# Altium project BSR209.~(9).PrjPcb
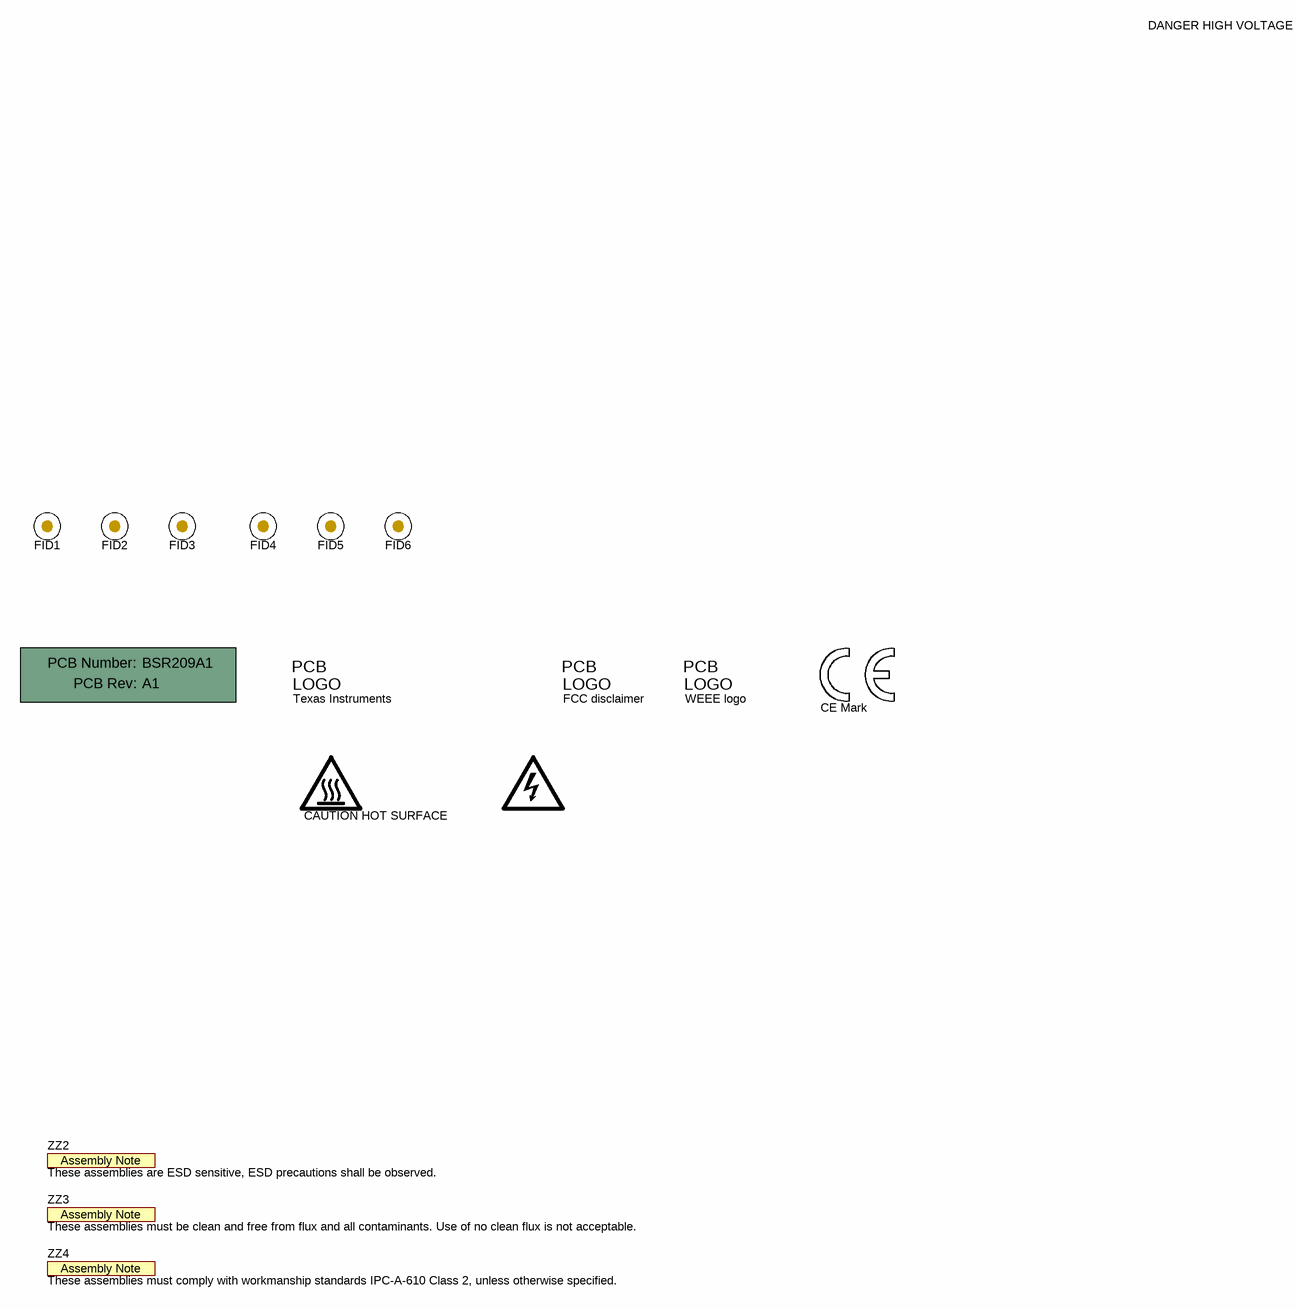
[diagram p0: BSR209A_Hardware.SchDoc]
EVM_orderable: LM5168FEVM; TID: N/A; TechSupport: http://www.ti.com/support; SCH_Rev: A1; PRJ_Title: LM5168FEVM; PRJ_Number: BSR209A1; PRJ_Engineer: FJD; PRJ_Customer: Public Release; PCB_Rev: A1; PCB_Layout: FJD; CopyrightYear: 2021
2 sheets, 69 parts. Net scope: global (net labels, ports and power ports of the same name join across sheets).
Board file: BSR209A_PCB.PcbDoc
Sheets:
  BSR209A_Hardware.SchDoc
  BSR209A_sch.SchDoc

## Sheet BSR209A_Hardware.SchDoc
size 431 x 279 mm; Date: Not shown in title block; ApprovedBy: Not shown in title block; CheckedBy: Not shown in title block; Author: Not shown in title block; CompanyName: Not shown in title block; Engineer: Not shown in title block; Organization: Not shown in title block; Address1: Not shown in title block; Address2: Not shown in title block; Address3: Not shown in title block; Address4: Not shown in title block; DocumentNumber: 1; Revision: Use project parameter SCH_Rev; SheetNumber: 2; SheetTotal: 2; PageSetup: Record=PageOptions¦CenterHorizontal=True¦CenterVertical=True¦PrintScale=1.00¦XCorrection=1.00¦YCorrection=1.00¦PrintKind=0¦BorderSize=5000000¦LeftOffset=0¦BottomOffset=0¦Orientation=2¦PaperLength=1000¦PaperWidth=1000¦Scale=100¦PaperSource=15¦PrintQuality=600¦MediaType=1¦DitherType=10¦PaperKind=Letter¦PrintScaleMode=1

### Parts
!PCB  Printed Circuit Board  (value not drawn)  (mechanical)
FID1  Fiducial  [Fiducial10-20]  (value not drawn)
FID2  Fiducial  [Fiducial10-20]  (value not drawn)
FID3  Fiducial  [Fiducial10-20]  (value not drawn)
FID4  Fiducial  [Fiducial10-20]  (value not drawn)
FID5  Fiducial  [Fiducial10-20]  (value not drawn)
FID6  Fiducial  [Fiducial10-20]  (value not drawn)
Logo1  Texas Instruments  [TI_Stacked_Overlay_Small]  (no BOM)
Logo2  CE Mark  [CE_Mark_10mm]  (no BOM)
Logo3  FCC disclaimer  [FCC_disclaimer]  (no BOM)
Logo4  WEEE logo  [WEEE_Minimum]  (no BOM)
Logo5  DANGER HIGH VOLTAGE  [IEC_HighVoltage_Small]  (no BOM)
Logo6  CAUTION HOT SURFACE  [IEC_HotSurface_Small]  (no BOM)
ZZ2  These assemblies are ESD sensitive, ESD precautions shall be observed.  [AssemblyNote]  (no BOM)
ZZ3  These assemblies must be clean and free from flux and all contaminants. Use of no clean flux is not acceptable.  [AssemblyNote]  (no BOM)
ZZ4  These assemblies must comply with workmanship standards IPC-A-610 Class 2, unless otherwise specified.  [AssemblyNote]  (no BOM)

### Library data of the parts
!PCB = CMP-0003618-2: Manufacturer: Any; PartNumber: BSR209A1; CompType: PCB
FID1-FID6 = CMP-0077181-1: Fiducial mark.  There is nothing to buy or mount.
Logo1 = CMP-0074838-1: Texas Instrument Corporate Signature; SymbolCreator: a0412235; Lib Reference: TI_Logo; Library Reference: Logo
Logo2 = CMP-0074844-1: SymbolCreator: a0412235
Logo3 = CMP-0074847-1: FCC_disclaimer; Library Reference: Logo
Logo4 = CMP-0074769-1
Logo5 = IEC_HighVoltage: IEC 61010-1 High Voltage Warning; SymbolCreator: a0412235
Logo6 = IEC_HotSurface: IEC 61010-1 Hot Surface Warning; SymbolCreator: a0412235
ZZ2 = CMP-0077236-1
ZZ3 = CMP-0077237-1
ZZ4 = CMP-0077238-1

## Sheet BSR209A_sch.SchDoc
size 431 x 279 mm; Date: Not shown in title block; ApprovedBy: Not shown in title block; CheckedBy: Not shown in title block; Author: Not shown in title block; CompanyName: Not shown in title block; Engineer: Not shown in title block; Organization: Not shown in title block; Address1: Not shown in title block; Address2: Not shown in title block; Address3: Not shown in title block; Address4: Not shown in title block; DocumentNumber: 1; Revision: Use project parameter SCH_Rev; SheetNumber: 1; SheetTotal: 2; PageSetup: Record=PageOptions¦CenterHorizontal=True¦CenterVertical=True¦PrintScale=0.96¦XCorrection=1.00¦YCorrection=1.00¦PrintKind=0¦BorderSize=5000000¦LeftOffset=0¦BottomOffset=0¦Orientation=2¦PaperLength=1000¦PaperWidth=1000¦Scale=100¦PaperSource=15¦PrintQuality=-3¦MediaType=1¦DitherType=10¦PrintScaleMode=1¦PaperKind=11×17¦PaperIndex=17
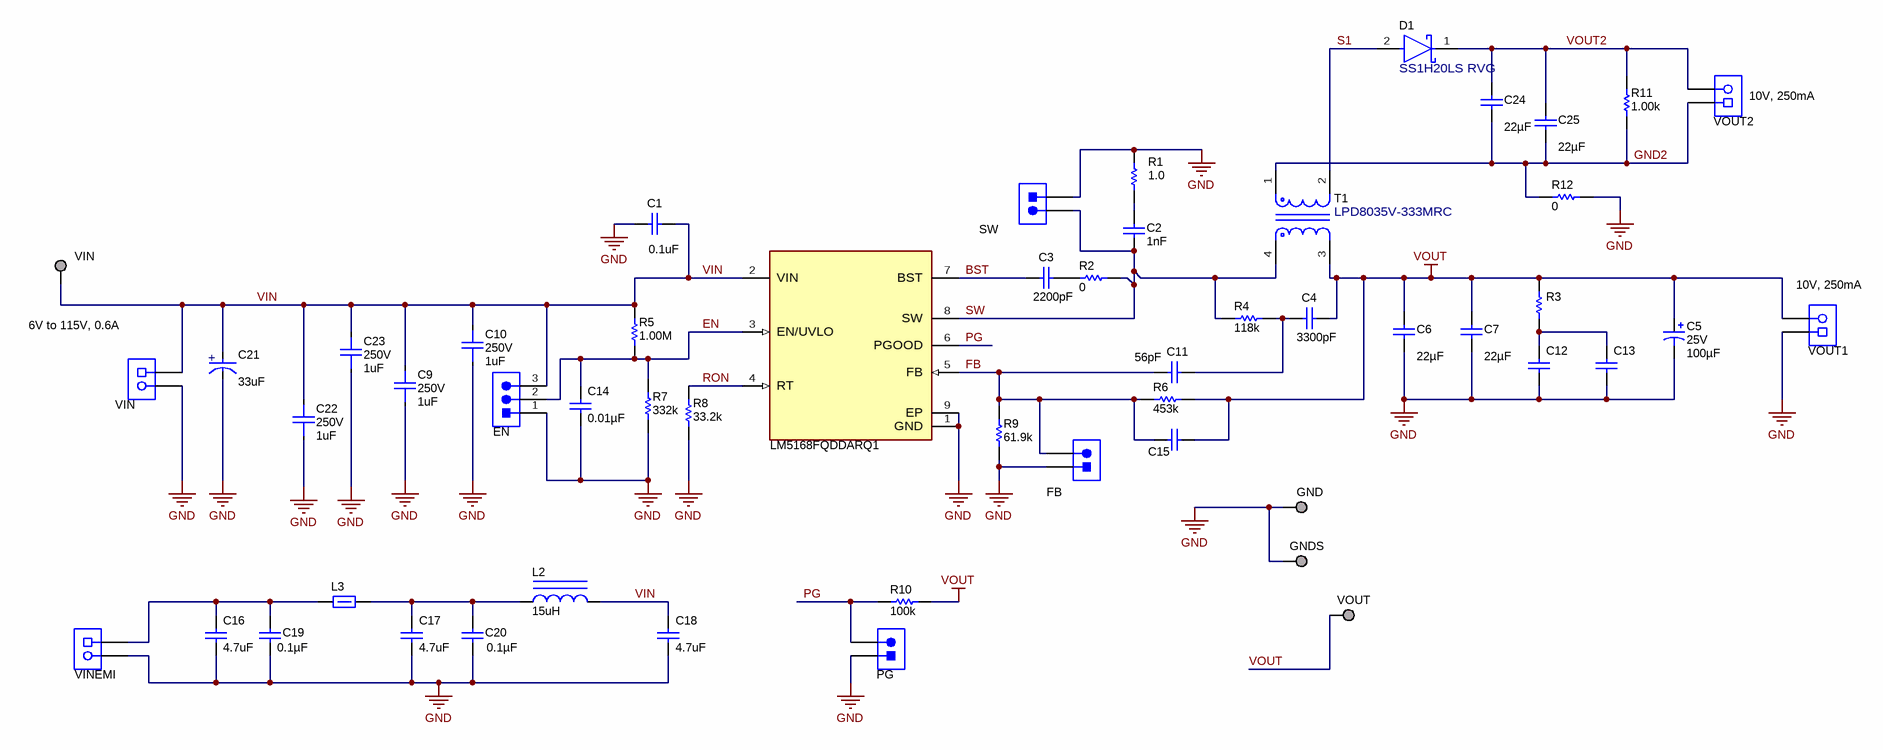
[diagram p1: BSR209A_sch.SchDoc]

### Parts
C1  ValueDisplayed: 0.1uF  [0805L]  (hidden comment: C2012X7T2E104K125AA)
C2  Cap_F: 1nF  [0603L]  (hidden comment: GRM188R72D102KW07D)
C3  ValueDisplayed: 2200pF  [0402S]  (hidden comment: GCM155R71H222KA37D)
C4  ValueDisplayed: 3300pF  [0603L]  (hidden comment: CR)
C5  VDC_V: 25V  ValueDisplayed: 100µF  [UWT_630x770]  (hidden comment: UWT1E101MCL1GS)
C6  ValueDisplayed: 22µF  [1210_270L]  (hidden comment: GRT32ER61E226KE13L)
C7  ValueDisplayed: 22µF  [1210_270L]  (hidden comment: GRT32ER61E226KE13L)
C9  VDC_V: 250V  ValueDisplayed: 1uF  [FP-CGA8P3X7T2E105K250KE_1812-MFG]  (hidden comment: CGA8P3X7T2E105K250KE)
C10  VDC_V: 250V  ValueDisplayed: 1uF  [FP-CGA8P3X7T2E105K250KE_1812-MFG]  (hidden comment: CGA8P3X7T2E105K250KE)
C11  ValueDisplayed: 56pF  [0603L]  (hidden comment: C0603C560J5GACTU)
C12  COUT3  [1210_270L]  (value not drawn)
C13  COUT4  [1210_270L]  (value not drawn)
C14  ValueDisplayed: 0.01µF  [0603L]  (hidden comment: CEN)
C15  CFF  [0603L]  (value not drawn)
C16  ValueDisplayed: 4.7uF  [1210_220]  (hidden comment: CGA6M3X7S2A475K200AB)
C17  ValueDisplayed: 4.7uF  [1210_220]  (hidden comment: CGA6M3X7S2A475K200AB)
C18  ValueDisplayed: 4.7uF  [1210_220]  (hidden comment: CGA6M3X7S2A475K200AB)
C19  ValueDisplayed: 0.1µF  [0603_HV]  (hidden comment: HMK107B7104KAHT)
C20  ValueDisplayed: 0.1µF  [0603_HV]  (hidden comment: HMK107B7104KAHT)
C21  ValueDisplayed: 33uF  [FP-ULT2C330MNL1GS_RADIAL-MFG]  (hidden comment: ULT2C330MNL1GS)
C22  VDC_V: 250V  ValueDisplayed: 1uF  [FP-CGA8P3X7T2E105K250KE_1812-MFG]  (hidden comment: CGA8P3X7T2E105K250KE)
C23  VDC_V: 250V  ValueDisplayed: 1uF  [FP-CGA8P3X7T2E105K250KE_1812-MFG]  (hidden comment: CGA8P3X7T2E105K250KE)
C24  ValueDisplayed: 22µF  [1210_270L]  (hidden comment: GRT32ER61E226KE13L)
C25  ValueDisplayed: 22µF  [1210_270L]  (hidden comment: GRT32ER61E226KE13L)
D1  SS1H20LS RVG  [FP-SS1H20LS RVG_SOD123HE-MFG]
J1  SW  [TSW-102-07-G-S]
J2  VOUT1  [TERM_BLK_ED555-2DS]
J3  VIN  [TERM_BLK_ED555-2DS]
J4  EN  [Samtec_HTSW-103-07-G-S]
J5  FB  [TSW-102-07-G-S]
J6  PG  [TSW-102-07-G-S]
J7  VINEMI  [TERM_BLK_ED555-2DS]
J8  VOUT2  [TERM_BLK_ED555-2DS]
L2  ValueDisplayed: 15uH  [MSS7341]  (hidden comment: MSS7341T-153MLB)
L3  FBMH3225HM202NT  [1210_280]  (value not drawn)
R1  ValueDisplayed: 1.0  [0603L]  (hidden comment: CRCW06031R00JNEA)
R2  ValueDisplayed: 0  [0402S]  (hidden comment: RBST)
R3  DNP  [2010]  (value not drawn)
R4  ValueDisplayed: 118k  [0603L]  (hidden comment: RC0603FR-07118KL)
R5  ValueDisplayed: 1.00M  [0603L]  (hidden comment: RC0603FR-071ML)
R6  ValueDisplayed: 453k  [0603L]  (hidden comment: RC0603FR-07453KL)
R7  ValueDisplayed: 332k  [0603L]  (hidden comment: RC0603FR-07332KL)
R8  ValueDisplayed: 33.2k  [0603L]  (hidden comment: RC0603FR-0733K2L)
R9  ValueDisplayed: 61.9k  [0603L]  (hidden comment: RC0603FR-0761K9L)
R10  ValueDisplayed: 100k  [0402S]  (hidden comment: ERJ-2RKF1003X)
R11  ValueDisplayed: 1.00k  [0805L]  (hidden comment: CRCW08051K00FKEA)
R12  ValueDisplayed: 0  [0603L]  (hidden comment: Rtie)
T1  LPD8035V-333MRC  [FP-LPD8035V-333MRC_SMD4-MFG]
TP1  VIN  [Harwin_S1751-46]
TP2  GND  [Keystone1598-2]
TP3  GNDS  [Keystone1598-2]
TP4  VOUT  [Keystone1598-2]
U1  LM5168FQDDARQ1  [DDA0008E-MFG]

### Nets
GND: C1.2 C5.2(-) C6.2 C7.2 C9.1 C10.1 C12.2 C13.2 C14.2 C16.2 C17.2 C18.2 C19.2 C20.2 C21.1(CATHODE) C22.1 C23.1 J1.1 J2.1 J3.2 J4.1 J5.1 J6.1 J7.2 R1.1 R7.1 R8.1 R9.1 R12.2 TP2.1 TP3.1 U1.1(GND) U1.9(EP)
VOUT: C4.1 C5.1(+) C6.1 C7.1 C15.1 J2.2 R3.2 R6.2 R10.2 T1.3 TP4.1
BST: C3.2 U1.7(BST)
EN: C14.1 J4.2 R5.1 R7.2 U1.3(EN/UVLO)
FB: C11.2 C15.2 J5.2 R6.1 R9.2 U1.5(FB)
GND2: C24.2 C25.2 J8.1 R11.1 R12.1 T1.1
PG: J6.2 R10.1 U1.6(PGOOD)
RON: R8.2 U1.4(RT)
S1: D1.2(ANODE) T1.2
SW: C2.2 J1.2 R2.2 R4.1 T1.4 U1.8(SW)
VIN: C1.1 C9.2 C10.2 C18.1 C21.2(ANODE) C22.2 C23.2 J3.1 J4.3 L2.2 R5.2 TP1.1 U1.2(VIN)
VOUT2: C24.1 C25.1 D1.1(CATHODE) J8.2 R11.2
NetC2_1: C2.1 R1.2
NetC3_1: C3.1 R2.1
NetC4_2: C4.2 C11.1 R4.2
NetC12_1: C12.1 C13.1 R3.1
NetC16_1: C16.1 C19.1 J7.1 L3.1
NetC17_1: C17.1 C20.1 L2.1 L3.2

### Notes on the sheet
- (near J8) 10V, 250mA
- (near J2) 10V, 250mA
- 6V to 115V, 0.6A

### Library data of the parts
C1 = CMP-0007897-1: CAP, CERM, 0.1 uF, 250 V, +/- 10%, X7T, 0805; Manufacturer: TDK; TaMin_C: -55°C; Polarized: N; SizeAreaWB_mm2: 6.75; Value1: Unknown; U/M: EA; Value: 0.1uF; TaMax_C: 125°C; SizeZ_mm: 1.45; SizeX_mm: 2; SizeY_mm: 1.25; Cap_Case: 0805; Value2: 250V; SizeArea_mm2: 2.5; CompType: Capacitor; Cap_F: 100nF; AEC Category: Q200
C2 = CMP-0081318-1: CAP, CERM, 1000 pF, 200 V,+/- 10%, X7R, 0603; Manufacturer: MuRata; SizeAreaWB_mm2: 4.68; SizeArea_mm2: 1.28; AEC Qualified: N; AEC Category: Q200; Value: 1000pF; TaMax_C: 125°C; SizeZ_mm: 1; TaMin_C: -55°C; VDC_V: 200V; SizeY_mm: 0.8; U/M: EA; CompType: Capacitor; SizeX_mm: 1.6; Cap_Case: 0603
C3 = CMP-0006357-2: CAP, CERM, 2200 pF, 50 V, +/- 10%, X7R, AEC-Q200 Grade 1, 0402; Manufacturer: MuRata; TaMin_C: -55°C; Polarized: N; SizeAreaWB_mm2: 3; Value1: Unknown; U/M: EA; Value: 2200pF; TaMax_C: 125°C; SizeZ_mm: 0.6; SizeX_mm: 1; SizeY_mm: 0.5; Cap_Case: 0402; Value2: 50V; CompType: Capacitor; AEC Qualified: Y; Cap_F: 2.2nF; AEC Category: Q200
C4 = CMP-0007087-4: CAP, CERM, 3300 pF, 100 V, +/- 10%, X7R, AEC-Q200 Grade 1, 0603; PartNumber: CGA3E2X7R2A332K080AA; Manufacturer: TDK; Polarized: N; CompType: Capacitor; Value: 3300pF; U/M: EA; Cap_F: 3.3nF; ESR_ohm: 6.62155d; Value1: 0.662155 ohm; VDC_V: 100V; IRMS_A: 3.0254dA; TaMin_C: -55°C; TaMax_C: 125°C; Cap_Case: 0603; SizeArea_mm2: 1.28; SizeAreaWB_mm2: 4.68; SizeX_mm: 1.6; SizeY_mm: 0.8; SizeZ_mm: 1; AEC Category: Q200; AEC Qualified: Y
C5 = CMP-0081462-1: CAP, AL, 100 µF, 25 V, +/- 20%, SMD; Manufacturer: Nichicon; TaMin_C: -55°C; Polarized: Y; SizeAreaWB_mm2: 77.4; U/M: EA; Value: 100uF; TaMax_C: 105°C; SizeZ_mm: 8; SizeX_mm: 7; SizeY_mm: 6.6; Cap_Case: 6.3x7.7mm; SizeArea_mm2: 46.2; CompType: Capacitor; AEC Qualified: N; IRMS_A: 91mA; AEC Category: Q200
C6 C7 C24 C25 = CMP-0084059-1: CAP, CERM, 22 µF, 25 V,+/- 10%, X5R, AEC-Q200 Grade 3, 1210; Manufacturer: MuRata; SizeAreaWB_mm2: 14.7; SizeArea_mm2: 8; AEC Qualified: Y; AEC Category: Q200; Value: 22uF; TaMax_C: 85°C; SizeZ_mm: 2.7; AEC Grade: 3; Polarized: N; TaMin_C: -55°C; VDC_V: 25V; SizeY_mm: 2.5; U/M: EA; CompType: Capacitor; SizeX_mm: 3.2; Cap_Case: 1210
C9 C10 C22 C23 = CMP-0091301-1: Cap Ceramic 1uF 250V X7T 10% Pad SMD 1812 +125°C Automotive T/R; Manufacturer: TDK; TempCo: +22/-33%; Cap_F: 1µF; AEC Qualified: Yes; Value: 1µF; AEC Grade: Grade 1; Tolerance_%: 0.1%; SizeZ_mm: 3.5mm
C11 = CMP-0006952-4: CAP, CERM, 56 pF, 50 V, +/- 5%, C0G/NP0, 0603; Manufacturer: Kemet; TaMin_C: -55°C; Polarized: N; SizeAreaWB_mm2: 4.68; Value1: Unknown; U/M: EA; Value: 56pF; TaMax_C: 125°C; SizeZ_mm: 1; SizeX_mm: 1.6; SizeY_mm: 0.8; Cap_Case: 0603; Value2: 50V; SizeArea_mm2: 1.28; CompType: Capacitor; AEC Category: Q200
C12 C13 = CMP-0009255-2: CAP, CERM, 22 uF, 25 V, +/- 10%, X7R, AEC-Q200 Grade 1, 1210; PartNumber: TMK325B7226KMHT; Manufacturer: Taiyo Yuden; Polarized: N; CompType: Capacitor; Value: 22uF; U/M: EA; Cap_F: 22µF; Value1: Unknown; VDC_V: 25V; TaMin_C: -55°C; TaMax_C: 125°C; Cap_Case: 1210; AEC Category: Q200; AEC Qualified: Y; AEC Grade: 1; SizeArea_mm2: 8; SizeAreaWB_mm2: 14.7; SizeX_mm: 3.2; SizeY_mm: 2.5; SizeZ_mm: 2.7
C14 = CMP-0080063-1: CAP, CERM, 0.01 µF, 100 V,+/- 10%, X8R, AEC-Q200 Grade 0, 0603; Manufacturer: TDK; PartNumber: CGA3E2X8R2A103K080AD; TaMin_C: -55°C; Polarized: N; SizeAreaWB_mm2: 4.68; U/M: EA; Value: 0.01uF; TaMax_C: 150°C; SizeZ_mm: 1; SizeX_mm: 1.6; SizeY_mm: 0.8; Cap_Case: 0603; Value2: 100V; SizeArea_mm2: 1.28; CompType: Capacitor; AEC Qualified: Y; Cap_F: 10nF; AEC Grade: 0; AEC Category: Q200
C15 = CMP-0006844-4: CAP, CERM, 1000 pF, 50 V, +/- 5%, X7R, AEC-Q200 Grade 1, 0603; Manufacturer: Kemet; PartNumber: C0603C102J5RACAUTO; TaMin_C: -55°C; Polarized: N; SizeAreaWB_mm2: 4.68; Value1: Unknown; U/M: EA; Value: 1000pF; TaMax_C: 125°C; SizeZ_mm: 1; SizeX_mm: 1.6; SizeY_mm: 0.8; Cap_Case: 0603; Value2: 50V; SizeArea_mm2: 1.28; CompType: Capacitor; AEC Qualified: Y; Cap_F: 1nF; AEC Category: Q200
C16-C18 = CMP-0009150-2: CAP, CERM, 4.7 uF, 100 V, +/- 10%, X7S, AEC-Q200 Grade 1, 1210; Manufacturer: TDK; TaMin_C: -55°C; ESR_ohm: 4.236m; Polarized: N; SizeAreaWB_mm2: 14.7; Value1: 0.004236 ohm; U/M: EA; Value: 4.7uF; TaMax_C: 125°C; SizeZ_mm: 2.2; SizeX_mm: 3.2; SizeY_mm: 2.5; Value2: 100V; SizeArea_mm2: 8; CompType: Capacitor; AEC Qualified: Y; Cap_F: 4.7µF; IRMS_A: 3.57337A; AEC Grade: 1; AEC Category: Q200
C19 C20 = CMP-0081011-1: CAP, CERM, 0.1 µF, 100 V,+/- 10%, X7R, AEC-Q200 Grade 1, 0603; Manufacturer: Taiyo Yuden; TaMin_C: -55°C; Polarized: N; SizeAreaWB_mm2: 4.68; U/M: EA; Value: 0.1uF; TaMax_C: 125°C; SizeZ_mm: 1; SizeX_mm: 1.6; SizeY_mm: 0.8; Cap_Case: 0603; Value2: 100V; SizeArea_mm2: 1.28; CompType: Capacitor; AEC Qualified: Y; Cap_F: 100nF; AEC Category: Q200
C21 = CMP-0091226-1: Aluminum Electrolytic Capacitors Radial 33uF 20% 160V, Can - SMD - 2000 Hrs @ 125°C; Manufacturer: Nichicon; Value: 33µF; AEC Qualified: Yes; IRMS_A: 65mA; Life: 2000Hours; Leakage Current: 311.2uA; AEC Grade: Grade 1; SizeZ_mm: 14.5mm
D1 = CMP-0093179-1: Rectifier Diode Schottky 200V 1A 2-Pin SOD-123HE T/R; Manufacturer: Taiwan Semiconductor; AEC Qualified: No; Peak Reverse Current: 1uA; SizeZ_mm: 0.85mm; TJmax_C: 150°C; Max Surge Forward Current: 30A
J1 J5 J6 = CMP-0075405-2: Header, 100mil, 2x1, Gold, TH; Manufacturer: Samtec; Current_A: 6.3A; Green_Lifecycle: Active; Shrouded: N; Gender: Male; Green_REACh: Passed; Voltage_V: 550V; Row_Count: 1; Pitch_mm: 2.54; Cert_UL: Y
J2 J3 J7 J8 = CMP-0074913-1: Terminal Block, 3.5mm Pitch, 2x1, TH; Manufacturer: On-Shore Technology; PartNumber: ED555/2DS; Cert_VDE: Y; CNHeader: False; Current_A: 6A; Green_Lifecycle: Active; Shrouded: N; Gender: Female; Green_REACh: Passed; Voltage_V: 150V; Row_Count: 1; Pitch_mm: 3.5; ContactFinish: Brass; CT: True
J4 = CMP-0075484-1: Header, 100mil, 3x1, Gold, TH; PartNumber: HTSW-103-07-G-S; Manufacturer: Samtec; Green_REACh: Passed; CT: False; Green_Lifecycle: Active; CNHeader: True
L2 = CMP-0061601-2: Inductor, Shielded Drum Core, Ferrite, 15 uH, 1.8 A, 0.05 ohm, AEC-Q200 Grade 1, SMD; Manufacturer: Coilcraft; Isat: 1.8A @ 30% inductance drop; Irms: 3A @ 40C rise; Green_Lifecycle: Not Set; SizeAreaWB_mm2: 86.49; DCR_ohm: 0.05; Green_REACh: Incomplete; Value: 15uH; Imax_A: 1.8A; SizeZ_mm: 4.1; SizeX_mm: 7.3; SizeArea_mm2: 53.29; Ind_H: 15µH; AEC Qualified: Y; AEC Grade: 1; AEC Category: Q200
L3 = CMP-0003373-1: Ferrite Bead, 2000 ohm @ 100 MHz, 1.2 A, 1210; Manufacturer: Taiyo Yuden; ZTyp@100MHz_Ohm: 2k; SizeAreaWB_mm2: 14.7; DCR_ohm: 1.3d; Value1: 0.13 ohm; Imax_A: 1.2A; SizeZ_mm: 2.8; SizeX_mm: 3.2; SizeY_mm: 2.5; SizeArea_mm2: 8
R1 = CMP-0025743-4: RES, 1.0, 5%, 0.1 W, AEC-Q200 Grade 0, 0603; Manufacturer: Vishay-Dale; Power_W: 100mW; TempCo: 200 ppm/C; Value_Code: 1R00; Value: 1.0; EIA_Code: E24; Res_ohm: 1; SizeX_mm: 1.6; SizeY_mm: 0.8; Value2: 0.1W; SizeArea_mm2: 1.28; CompType: Resistor; AEC Qualified: Y; VDC_V: 75V; AEC Category: Q200; AEC Grade: 0
R2 = CMP-0026822-3: RES, 0, 5%, 0.063 W, AEC-Q200 Grade 0, 0402; Manufacturer: Vishay-Dale; PartNumber: CRCW04020000Z0ED; Power_W: 63mW; TempCo: 200 ppm/C; Value_Code: 0000; Value: 0; EIA_Code: E24; SizeX_mm: 1; SizeY_mm: 0.5; SizeZ_mm: 0.6; Value2: 0.063W; CompType: Resistor; AEC Qualified: Y; VDC_V: 50V; AEC Category: Q200
R3 = CMP-0016525-2: RES, 0.2, 1%, 1 W, 2010; Manufacturer: Stackpole Electronics Inc; PartNumber: CSRN2010FKR200; Power_W: 1W; TempCo: 250 ppm/C; Value_Code: R200; U/M: EA; Value: 0.2; EIA_Code: E96; Res_ohm: 2d; SizeX_mm: 5; SizeY_mm: 2.5; SizeZ_mm: 1.66; SizeArea_mm2: 12.5; CompType: Resistor; AEC Category: Q200
R4 = CMP-0022758-4: RES, 118 k, 1%, 0.1 W, 0603; Manufacturer: Yageo; Power_W: 100mW; TempCo: 100 ppm/C; Value: 118k; EIA_Code: E96; SizeX_mm: 1.6; SizeY_mm: 0.8; SizeZ_mm: 1; Value2: 0.1W; SizeArea_mm2: 1.28; CompType: Resistor; AEC Qualified: N; VDC_V: 75V; AEC Category: Q200; SizeAreaWB_mm2: 4.68
R5 = CMP-0022899-4: RES, 1.00 M, 1%, 0.1 W, 0603; Manufacturer: Yageo; Power_W: 100mW; TempCo: 100 ppm/C; Value_Code: 1M00; Value: 1.00Meg; EIA_Code: E96; Res_ohm: 1M; SizeX_mm: 1.6; SizeY_mm: 0.8; SizeZ_mm: 1; Value2: 0.1W; SizeArea_mm2: 1.28; CompType: Resistor; AEC Qualified: N; VDC_V: 75V; AEC Category: Q200; SizeAreaWB_mm2: 4.68
R6 = CMP-0023120-4: RES, 453 k, 1%, 0.1 W, 0603; Manufacturer: Yageo; Power_W: 100mW; TempCo: 100 ppm/C; Value: 453k; EIA_Code: E96; SizeX_mm: 1.6; SizeY_mm: 0.8; SizeZ_mm: 1; Value2: 0.1W; SizeArea_mm2: 1.28; CompType: Resistor; AEC Qualified: N; VDC_V: 75V; AEC Category: Q200; SizeAreaWB_mm2: 4.68
R7 = CMP-0023034-4: RES, 332 k, 1%, 0.1 W, 0603; Manufacturer: Yageo; Power_W: 100mW; TempCo: 100 ppm/C; Value: 332k; EIA_Code: E96; SizeX_mm: 1.6; SizeY_mm: 0.8; SizeZ_mm: 1; Value2: 0.1W; SizeArea_mm2: 1.28; CompType: Resistor; AEC Qualified: N; VDC_V: 75V; AEC Category: Q200; SizeAreaWB_mm2: 4.68
R8 = CMP-0023036-5: RES, 33.2 k, 1%, 0.1 W, 0603; Manufacturer: Yageo; Power_W: 100mW; TempCo: 100 ppm/C; Value_Code: 33k2; Value: 33.2k; EIA_Code: E96; SizeX_mm: 1.6; SizeY_mm: 0.8; SizeZ_mm: 1; Value2: 0.1W; SizeArea_mm2: 1.28; CompType: Resistor; AEC Qualified: N; VDC_V: 75V; AEC Category: Q200; SizeAreaWB_mm2: 4.68
R9 = CMP-0023216-5: RES, 61.9 k, 1%, 0.1 W, 0603; Manufacturer: Yageo; Power_W: 100mW; TempCo: 100 ppm/C; Value_Code: 61k9; Value: 61.9k; EIA_Code: E96; SizeX_mm: 1.6; SizeY_mm: 0.8; SizeZ_mm: 1; Value2: 0.1W; SizeArea_mm2: 1.28; CompType: Resistor; AEC Qualified: N; VDC_V: 75V; AEC Category: Q200; SizeAreaWB_mm2: 4.68
R10 = CMP-0026659-1: RES, 100 k, 1%, 0.1 W, 0402; Manufacturer: Panasonic; Power_W: 100mW; TempCo: 100 ppm/C; U/M: EA; Value: 100k; EIA_Code: E96; SizeX_mm: 1; SizeY_mm: 0.5; SizeZ_mm: 0.6; Value2: 0.1W; CompType: Resistor; VDC_V: 50V; AEC Category: Q200
R11 = CMP-0020951-3: RES, 1.00 k, 1%, 0.125 W, AEC-Q200 Grade 0, 0805; Manufacturer: Vishay-Dale; Power_W: 125mW; TempCo: 100 ppm/C; Value_Code: 1k00; Value: 1.00k; EIA_Code: E96; Res_ohm: 1k; SizeX_mm: 2; SizeY_mm: 1.25; SizeZ_mm: 1.45; Value2: 0.125W; SizeArea_mm2: 2.5; CompType: Resistor; AEC Qualified: Y; VDC_V: 150V; AEC Category: Q200; AEC Grade: 0
R12 = CMP-0025697-4: RES, 0, 5%, 0.1 W, AEC-Q200 Grade 0, 0603; Manufacturer: Vishay-Dale; PartNumber: CRCW06030000Z0EA; Power_W: 100mW; TempCo: 200 ppm/C; Value_Code: 0000; Value: 0; EIA_Code: E24; SizeX_mm: 1.6; SizeY_mm: 0.8; SizeZ_mm: 1; Value2: 0.1W; SizeArea_mm2: 1.28; CompType: Resistor; AEC Qualified: Y; VDC_V: 75V; AEC Category: Q200
T1 = CMP-0091289-1: Power inductor, coupled, shielded, 20% tol, RoHS, halogen-free; Manufacturer: Coilcraft; Rsec1_ohm: 6.17d; AEC Grade: Grade 3; AEC Qualified: Yes; Voltage_Isolation_Vrms: 1500Vrms; Ind_H: 26.4µH; Ns1toNp: 1:1; TaMax_C: +85°C; TaMin_C: -40°C; SizeZ_mm: 3.5mm
TP1 = CMP-0075188-1: Test Lead clips and hooks, SMT; Manufacturer: Harwin; PartNumber: S1751-46; CNHeader: False; Current_A: 2A; CompType: Test Point; ContactFinish: Tin; CT: True
TP2-TP4 = 1598-2: Terminal, Turret, TH, Triple; Manufacturer: Keystone; CompType: Turret Terminal; U/M: EA
U1 = CMP-0092717-1: 0.3-A, 120-V, Step-Down Converter with Fly-buck Capability, HSOIC8; Manufacturer: Texas Instruments; AEC Qualified: Yes; Output Type: AdjustableProgrammable; Switching Frequency: 1MHz; Standoff Height: 0mm; Max Supply Voltage: 115V; Nominal Supply Current: 10-420uA; Min Supply Voltage: 6V; Number Of Outputs: 1; TJmax_C: +150°C; SizeZ_mm: 1.7mm; Switching Topology: Buck; Max Duty Cycle: 100%

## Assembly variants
001: not fitted C2 C5 C12 C13 C14 C15 C18 C25 FID1 FID2 FID3 FID4 FID5 FID6 J4 J5 L2 R1 R3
